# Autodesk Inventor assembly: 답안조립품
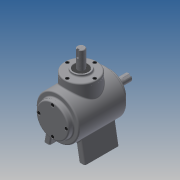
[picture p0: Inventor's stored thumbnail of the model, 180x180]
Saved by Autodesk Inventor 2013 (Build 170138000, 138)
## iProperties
Created: 2015-01
Part Number: 답안조립품
Document SubType Name: Assembly
Designer: kb543
Author: kb543
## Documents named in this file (15)
- C:\Users\kb543\Desktop\450105V1029\답안조립품.iam
- C:\Users\kb543\Desktop\450105V1029\1-본체.ipt
- C:\Users\kb543\Desktop\450105V1029\M4.ipt
- C:\Users\kb543\Desktop\450105V1029\메인 베벨기어.ipt
- C:\Users\kb543\Desktop\450105V1029\메인 축.ipt
- 메인 축.ipt
- C:\Users\kb543\Desktop\450105V1029\베어링 6203.ipt
- C:\Users\kb543\Desktop\450105V1029\서브 베벨기어.ipt
- C:\Users\kb543\Desktop\450105V1029\서브 축.ipt
- 서브 축.ipt
- C:\Users\kb543\Desktop\450105V1029\오일실.ipt
- C:\Users\kb543\Desktop\450105V1029\커버.ipt
- C:\Users\kb543\Desktop\450105V1029\커버2.ipt
- C:\Users\kb543\Desktop\450105V1029\키 4x4.ipt
- C:\Users\kb543\Desktop\450105V1029\키 5x5.ipt
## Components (13 placed, 2 different names)
1. 1-본체:1
2. M4:1
3. M4:4
4. M4:5
5. M4:6
6. M4:3
7. M4:7
8. M4:8
9. M4:9
10. M4:2
11. M4:10
12. M4:11
13. M4:12
